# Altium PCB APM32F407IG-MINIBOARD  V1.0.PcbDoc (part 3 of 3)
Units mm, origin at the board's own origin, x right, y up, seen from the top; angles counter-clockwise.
Board outline 442.79 x 366.46 mm, 2 copper layers (Top Layer, Bottom Layer); 220 components, 190 nets, 1232 pads, 648 vias.
Unrouted connection lines stored in the file: 190.
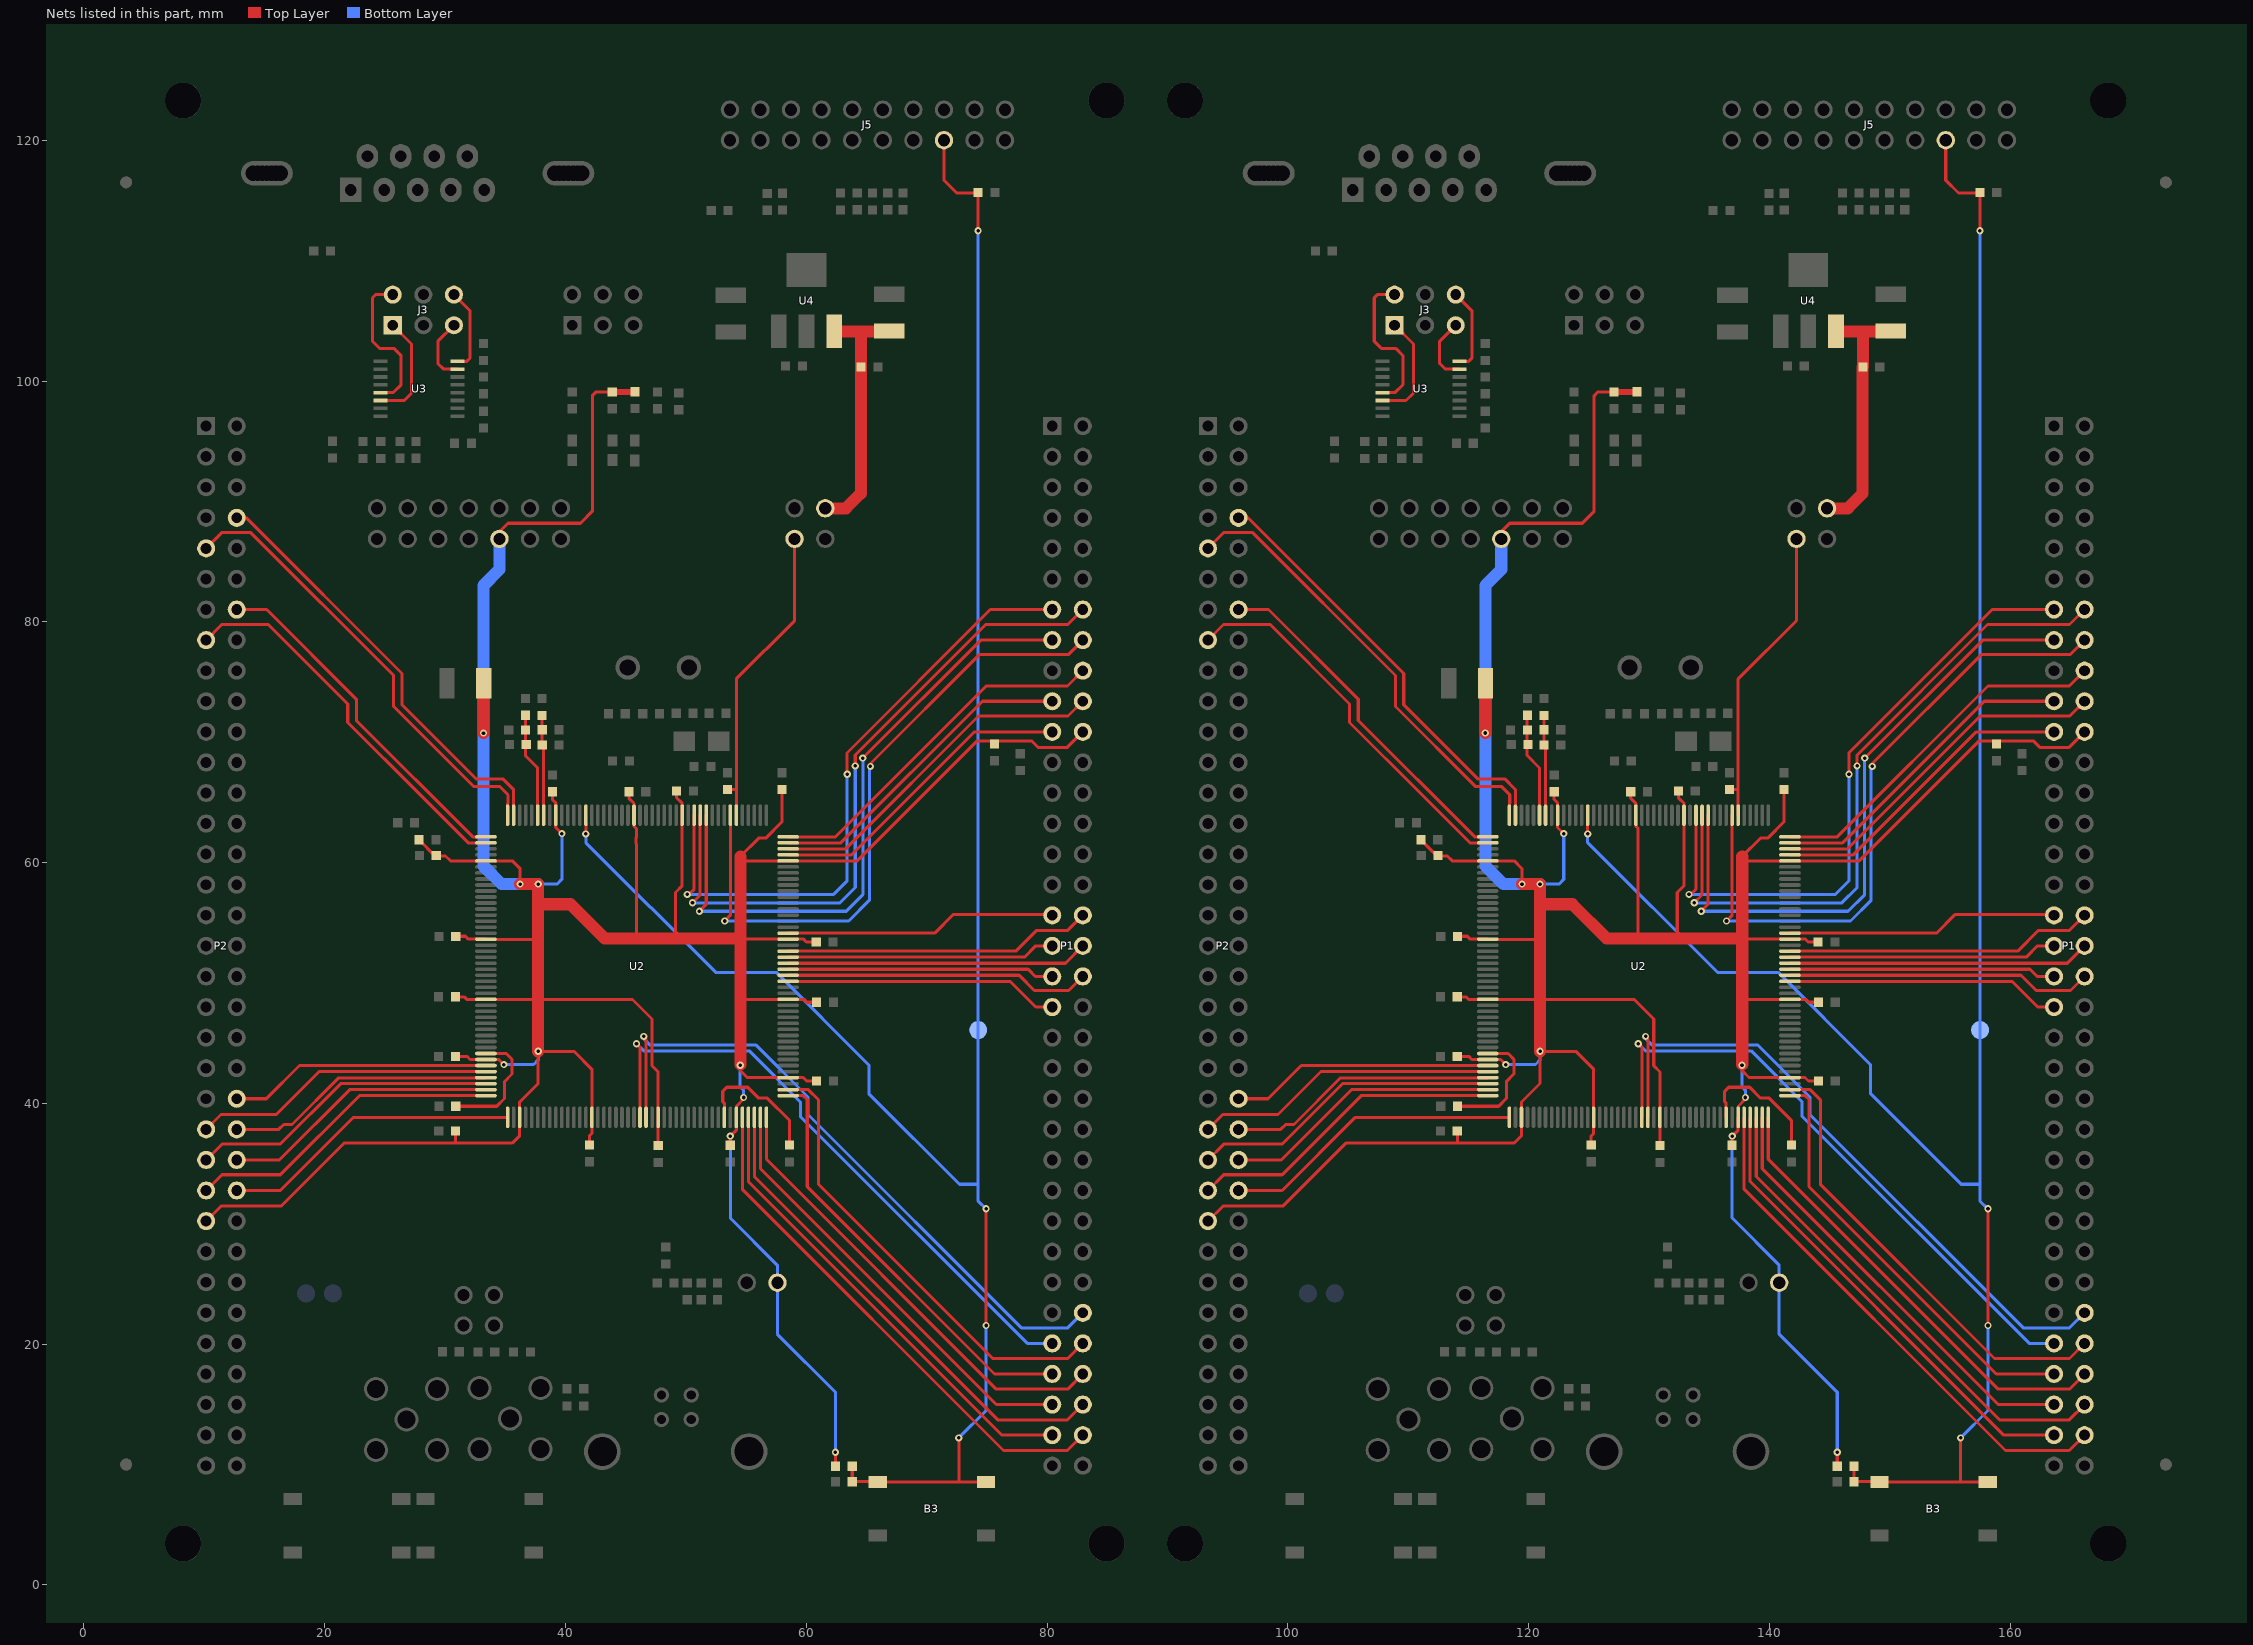
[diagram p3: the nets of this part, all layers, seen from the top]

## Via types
v1: diameter 0.6, hole 0.3, Top Layer to Bottom Layer, 648 vias

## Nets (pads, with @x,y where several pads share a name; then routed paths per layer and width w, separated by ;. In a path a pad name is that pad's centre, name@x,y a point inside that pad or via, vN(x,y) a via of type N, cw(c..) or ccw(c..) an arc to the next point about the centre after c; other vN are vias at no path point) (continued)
PG7: P1.61 U2.111 | length 103.6
  Top Layer w0.254: v1(45.896,44.96) 46.2,44.656 46.2,38.85 U2.111@46.19,38.84 ; v1(129.116,44.96) 129.42,44.656 129.42,38.85 U2.111@129.41,38.84
  Bottom Layer w0.254: v1(45.896,44.96) 46.496,44.36 55.27,44.36 59.51,40.12 59.51,38.91 78.359,20.061 P1.61@80.431,20.061 ; v1(129.116,44.96) 129.716,44.36 138.49,44.36 142.73,40.12 142.73,38.91 161.579,20.061 P1.61@163.651,20.061
PG8: P1.60 U2.112 | length 109
  Top Layer w0.254: U2.112@46.69,38.84 46.7,38.85 46.7,45.334 ; U2.112@129.91,38.84 129.92,38.85 129.92,45.334
  Bottom Layer w0.254: v1(46.5,45.56) 46.5,45.36 47,44.86 55.8,44.86 60.14,40.52 60.14,39.07 77.86,21.35 81.72,21.35 P1.60@82.971,22.601 ; v1(129.72,45.56) 129.72,45.36 130.22,44.86 139.02,44.86 143.36,40.52 143.36,39.07 161.08,21.35 164.94,21.35 P1.60@166.191,22.601
PG9: P1.39 U2.152 | length 45.7
  Top Layer w0.254: U2.152@58.49,50.14 76.93,50.14 79.069,48.001 P1.39@80.431,48.001 ; U2.152@141.71,50.14 160.15,50.14 162.289,48.001 P1.39@163.651,48.001
PG10: P1.38 U2.153 | length 51
  Top Layer w0.254: U2.153@58.49,50.64 77.68,50.64 78.95,49.37 81.8,49.37 P1.38@82.971,50.541 ; U2.153@141.71,50.64 160.9,50.64 162.17,49.37 165.02,49.37 P1.38@166.191,50.541
PG11: P1.37 U2.154 | length 44.4
  Top Layer w0.254: U2.154@58.49,51.14 78.43,51.14 79.03,50.541 P1.37@80.431,50.541 ; U2.154@141.71,51.14 161.65,51.14 162.25,50.541 P1.37@163.651,50.541
PG12: P1.36 U2.155 | length 50.2
  Top Layer w0.254: U2.155@58.49,51.64 81.53,51.64 P1.36@82.971,53.081 ; U2.155@141.71,51.64 164.75,51.64 P1.36@166.191,53.081
PG13: P1.35 U2.156 | length 44.7
  Top Layer w0.254: U2.156@58.49,52.14 78.12,52.14 79.061,53.081 P1.35@80.431,53.081 ; U2.156@141.71,52.14 161.34,52.14 162.281,53.081 P1.35@163.651,53.081
PG14: P1.34 U2.157 | length 51.4
  Top Layer w0.254: U2.157@58.49,52.64 77.41,52.64 79.14,54.37 81.72,54.37 P1.34@82.971,55.621 ; U2.157@141.71,52.64 160.63,52.64 162.36,54.37 164.94,54.37 P1.34@166.191,55.621
PG15: P1.33 U2.160 | length 45.2
  Top Layer w0.254: U2.160@58.49,54.14 60.306,54.14 60.307,54.141 70.661,54.141 72.19,55.67 80.381,55.67 P1.33@80.431,55.621 ; U2.160@141.71,54.14 143.526,54.14 143.527,54.141 153.881,54.141 155.41,55.67 163.601,55.67 P1.33@163.651,55.621
PH2: P2.8 U2.43 | length 72
  Top Layer w0.254: P2.8@12.69,88.641 13.479,88.641 26.41,75.71 26.41,73.11 32.558,66.961 34.788,66.961 35.69,66.06 U2.43@35.69,63.94 ; P2.8@95.91,88.641 96.699,88.641 109.63,75.71 109.63,73.11 115.778,66.962 118.008,66.962 118.91,66.06 U2.43@118.91,63.94
PH3: P2.9 U2.44 | length 75.7
  Top Layer w0.254: P2.9@10.15,86.101 11.486,87.437 13.823,87.437 25.72,75.54 25.72,72.96 32.35,66.33 34.51,66.33 35.217,65.623 35.217,64.94 35.19,64.913 U2.44@35.19,63.94 ; P2.9@93.37,86.101 94.706,87.437 97.043,87.437 108.94,75.54 108.94,72.96 115.57,66.33 117.73,66.33 118.437,65.623 118.437,64.94 118.41,64.913 U2.44@118.41,63.94
PH4: P2.14 U2.45 | length 59.1
  Top Layer w0.254: P2.14@12.69,81.021 15.179,81.021 22.63,73.57 22.63,71.81 32.3,62.14 U2.45@33.39,62.14 ; P2.14@95.91,81.021 98.399,81.021 105.85,73.57 105.85,71.81 115.52,62.14 U2.45@116.61,62.14
PH5: P2.15 U2.46 | length 64.4
  Top Layer w0.254: P2.15@10.15,78.481 11.439,79.77 15.32,79.77 21.91,73.18 21.91,71.64 27.88,65.67 31.91,61.64 U2.46@33.39,61.64 ; P2.15@93.37,78.481 94.659,79.77 98.54,79.77 105.13,73.18 105.13,71.64 111.1,65.67 115.13,61.64 U2.46@116.61,61.64
PH6: P2.46 U2.83 | length 43.7
  Top Layer w0.254: P2.46@12.701,40.37 P2.46@12.69,40.381 15.141,40.381 17.9,43.14 U2.83@33.39,43.14 ; P2.46@95.921,40.37 P2.46@95.91,40.381 98.361,40.381 101.12,43.14 U2.83@116.61,43.14
PH7: P2.47 U2.84 | length 50.5
  Top Layer w0.254: P2.47@10.15,37.841 11.379,39.07 15.97,39.07 19.54,42.64 U2.84@33.39,42.64 ; P2.47@93.37,37.841 94.599,39.07 99.19,39.07 102.76,42.64 U2.84@116.61,42.64
PH8: P2.48 U2.85 | length 45.2
  Top Layer w0.254: P2.48@12.761,37.77 P2.48@12.69,37.841 16.191,37.841 16.6,38.25 17.288,38.25 21.155,42.117 33.367,42.117 U2.85@33.39,42.14 ; P2.48@95.981,37.77 P2.48@95.91,37.841 99.411,37.841 99.82,38.25 100.508,38.25 104.375,42.117 116.587,42.117 U2.85@116.61,42.14
PH9: P2.49 U2.86 | length 51.7
  Top Layer w0.254: P2.49@10.15,35.301 11.459,36.61 16.29,36.61 21.32,41.64 U2.86@33.39,41.64 ; P2.49@93.37,35.301 94.679,36.61 99.51,36.61 104.54,41.64 U2.86@116.61,41.64
PH10: P2.50 U2.87 | length 46.2
  Top Layer w0.254: P2.50@12.69,35.301 16.231,35.301 22.07,41.14 U2.87@33.39,41.14 ; P2.50@95.91,35.301 99.451,35.301 105.29,41.14 U2.87@116.61,41.14
PH11: P2.51 U2.88 | length 53
  Top Layer w0.254: P2.51@10.15,32.761 11.459,34.07 16.31,34.07 22.88,40.64 U2.88@33.39,40.64 ; P2.51@93.37,32.761 94.679,34.07 99.53,34.07 106.1,40.64 U2.88@116.61,40.64
PH12: P2.52 U2.89 | length 50
  Top Layer w0.254: P2.52@12.69,32.761 16.311,32.761 22.39,38.84 U2.89@35.19,38.84 ; P2.52@95.91,32.761 99.531,32.761 105.61,38.84 U2.89@118.41,38.84
PH13: P1.68 U2.128 | length 87.6
  Top Layer w0.254: U2.128@54.69,38.84 54.69,32.86 76.39,11.16 81.69,11.16 P1.68@82.971,12.441 ; U2.128@137.91,38.84 137.91,32.86 159.61,11.16 164.91,11.16 P1.68@166.191,12.441
PH14: P1.67 U2.129 | length 78.6
  Top Layer w0.254: U2.129@55.19,38.84 55.19,33.51 76.259,12.441 P1.67@80.431,12.441 ; U2.129@138.41,38.84 138.41,33.51 159.479,12.441 P1.67@163.651,12.441
PH15: P1.66 U2.130 | length 82.2
  Top Layer w0.254: U2.130@55.69,38.84 55.69,33.92 75.9,13.71 81.7,13.71 P1.66@82.971,14.981 ; U2.130@138.91,38.84 138.91,33.92 159.12,13.71 164.92,13.71 P1.66@166.191,14.981
PI0: P1.65 U2.131 | length 73.2
  Top Layer w0.254: U2.131@56.19,38.84 56.19,34.58 75.789,14.981 P1.65@80.431,14.981 ; U2.131@139.41,38.84 139.41,34.58 159.009,14.981 P1.65@163.651,14.981
PI1: P1.64 U2.132 | length 76.4
  Top Layer w0.254: U2.132@56.69,38.84 56.69,35.36 75.79,16.26 81.71,16.26 P1.64@82.971,17.521 ; U2.132@139.91,38.84 139.91,35.36 159.01,16.26 164.93,16.26 P1.64@166.191,17.521
PI2: P1.63 U2.133 | length 71.5
  Top Layer w0.254: U2.133@58.49,40.64 59.76,40.64 60.08,40.32 60.08,33.08 75.639,17.521 P1.63@80.431,17.521 ; U2.133@141.71,40.64 142.98,40.64 143.3,40.32 143.3,33.08 158.859,17.521 P1.63@163.651,17.521
PI3: P1.62 U2.134 | length 76.7
  Top Layer w0.254: U2.134@58.49,41.14 60.17,41.14 61.02,40.29 61.02,33.28 75.49,18.81 81.72,18.81 P1.62@82.971,20.061 ; U2.134@141.71,41.14 143.39,41.14 144.24,40.29 144.24,33.28 158.71,18.81 164.94,18.81 P1.62@166.191,20.061
PI4: P1.21 U2.173 | length 52.3
  Top Layer w0.254: U2.173@58.49,60.64 63.75,60.64 73.971,70.861 P1.21@80.431,70.861 ; U2.173@141.71,60.64 146.97,60.64 157.191,70.861 P1.21@163.651,70.861
PI5: P1.20 U2.174 | length 59.1
  Top Layer w0.254: U2.174@58.49,61.14 63.27,61.14 74.3,72.17 81.74,72.17 P1.20@82.971,73.401 ; U2.174@141.71,61.14 146.49,61.14 157.52,72.17 164.96,72.17 P1.20@166.191,73.401
PI6: P1.19 U2.175 | length 53.6
  Top Layer w0.254: U2.175@58.49,61.64 62.87,61.64 74.631,73.401 P1.19@80.431,73.401 ; U2.175@141.71,61.64 146.09,61.64 157.851,73.401 P1.19@163.651,73.401
PI7: P1.18 U2.176 | length 60.4
  Top Layer w0.254: U2.176@58.49,62.14 62.42,62.14 74.95,74.67 81.7,74.67 P1.18@82.971,75.941 ; U2.176@141.71,62.14 145.64,62.14 158.17,74.67 164.92,74.67 P1.18@166.191,75.941
PI8: P1.16 U2.7 | length 110.1
  Top Layer w0.254: v1(53.22,55.15) 53.69,55.62 U2.7@53.69,63.94 ; v1(65.33,67.99) 65.33,68.227 74.373,77.27 81.76,77.27 P1.16@82.971,78.481 ; v1(136.44,55.15) 136.91,55.62 U2.7@136.91,63.94 ; v1(148.55,67.99) 148.55,68.227 157.593,77.27 164.98,77.27 P1.16@166.191,78.481
  Bottom Layer w0.254: v1(53.22,55.15) 63.52,55.15 65.24,56.87 65.24,67.98 65.25,67.99 v1(65.33,67.99) ; v1(136.44,55.15) 146.74,55.15 148.46,56.87 148.46,67.98 148.47,67.99 v1(148.55,67.99)
PI9: P1.15 U2.11 | length 112.5
  Top Layer w0.254: v1(51.12,55.96) 51.69,56.53 U2.11@51.69,63.94 ; v1(64.7,68.68) 74.501,78.481 P1.15@80.431,78.481 77.691,78.481 ; v1(134.34,55.96) 134.91,56.53 U2.11@134.91,63.94 ; v1(147.92,68.68) 157.721,78.481 P1.15@163.651,78.481 160.911,78.481
  Bottom Layer w0.254: v1(51.12,55.96) 63.32,55.96 64.697,57.337 64.697,68.677 v1(64.7,68.68) ; v1(134.34,55.96) 146.54,55.96 147.917,57.337 147.917,68.677 v1(147.92,68.68)
PI10: P1.14 U2.12 | length 113
  Top Layer w0.254: v1(50.55,56.66) 51.19,57.3 U2.12@51.19,63.94 ; v1(64.07,68.03) 64.07,68.937 74.903,79.77 81.72,79.77 P1.14@82.971,81.021 ; v1(133.77,56.66) 134.41,57.3 U2.12@134.41,63.94 ; v1(147.29,68.03) 147.29,68.937 158.123,79.77 164.94,79.77 P1.14@166.191,81.021
  Bottom Layer w0.254: v1(50.55,56.66) 62.8,56.66 64.07,57.93 v1(64.07,68.03) ; v1(133.77,56.66) 146.02,56.66 147.29,57.93 v1(147.29,68.03)
PI11: P1.13 U2.13 | length 106.6
  Top Layer w0.254: v1(50.11,57.36) 50.26,57.36 50.69,57.79 U2.13@50.69,63.94 ; v1@63.38,67.317 63.38,69.11 75.291,81.021 P1.13@80.431,81.021 ; v1(133.33,57.36) 133.48,57.36 133.91,57.79 U2.13@133.91,63.94 ; v1@146.6,67.317 146.6,69.11 158.511,81.021 P1.13@163.651,81.021
  Bottom Layer w0.254: v1(50.11,57.36) 62.27,57.36 63.4,58.49 v1(63.4,67.34) ; v1(133.33,57.36) 145.49,57.36 146.62,58.49 v1(146.62,67.34)
T-RESET#: B3.2 B3.3 C3.2 J5.15 R5.2 R26.1 TP7.1 U2.31 | length 349.4
  Top Layer w0.254: v1(41.69,62.38) U2.31@41.69,63.24 ; R5.2@63.82,9.85 C3.2@63.82,8.57 65.917,8.57 B3.2@65.93,8.557 72.66,8.557 ; J5.15@71.434,120.005 71.434,116.669 72.49,115.613 74.23,115.613 R26.1@74.272,115.655 v1(74.272,112.482) ; v1(72.67,12.21) 72.67,8.567 72.66,8.557 ; B3.3@74.93,8.557 72.66,8.557 ; v1(74.94,21.55) v1(74.94,31.25) ; v1(124.91,62.38) U2.31@124.91,63.24 ; R5.2@147.04,9.85 C3.2@147.04,8.57 149.137,8.57 B3.2@149.15,8.557 155.88,8.557 ; J5.15@154.654,120.005 154.654,116.669 155.71,115.613 157.45,115.613 R26.1@157.492,115.655 v1(157.492,112.482) ; v1(155.89,12.21) 155.89,8.567 155.88,8.557 ; B3.3@158.15,8.557 155.88,8.557 ; v1(158.16,21.55) v1(158.16,31.25)
  Bottom Layer w0.254: v1(41.69,62.38) 41.69,61.66 52.47,50.88 57.51,50.88 65.2,43.19 65.2,40.8 72.72,33.28 74.282,33.28 ; v1(72.67,12.21) 74.94,14.48 v1(74.94,21.55) ; 74.262,36.24 74.282,36.22 ; v1(74.272,112.482) 74.282,112.472 TP7.1@74.282,46.09 74.282,36.22 ; v1@74.925,31.235 74.282,31.878 74.282,33.28 ; v1(124.91,62.38) 124.91,61.66 135.69,50.88 140.73,50.88 148.42,43.19 148.42,40.8 155.94,33.28 157.502,33.28 ; v1(155.89,12.21) 158.16,14.48 v1(158.16,21.55) ; 157.482,36.24 157.502,36.22 ; v1(157.492,112.482) 157.502,112.472 TP7.1@157.502,46.09 157.502,36.22 ; v1@158.145,31.235 157.502,31.878 157.502,33.28 ; 74.282,33.28 74.282,36.22 ; 157.502,33.28 157.502,36.22
T-VBAT: C28.2 J9.2 U2.6 | length 51.4
  Top Layer w0.254: C28.2@53.46,66.07 54.18,66.07 54.19,66.06 ; U2.6@54.19,63.94 54.19,66.06 ; J9.2@59.03,86.89 59.03,80.1 54.19,75.26 54.19,66.06 ; C28.2@136.68,66.07 137.4,66.07 137.41,66.06 ; U2.6@137.41,63.94 137.41,66.06 ; J9.2@142.25,86.89 142.25,80.1 137.41,75.26 137.41,66.06
U1_RX: J3.2 U3.13 | length 25.4
  Top Layer w0.254: U3.13@24.635,99.034 25.673,99.034 26.344,99.705 26.344,102.105 25.734,102.715 24.544,102.715 23.96,103.299 23.96,106.915 24.222,107.177 J3.2@25.651,107.177 J3.2@25.623,107.205 ; U3.13@107.855,99.034 108.893,99.034 109.564,99.705 109.564,102.105 108.954,102.715 107.764,102.715 107.18,103.299 107.18,106.915 107.442,107.177 J3.2@108.871,107.177 J3.2@108.843,107.205
U1_TX: J3.1 U3.14 | length 18.5
  Top Layer w0.254: U3.14@24.635,98.384 26.603,98.384 27.214,98.995 27.214,103.073 J3.1@25.651,104.637 ; U3.14@107.855,98.384 109.823,98.384 110.434,98.995 110.434,103.073 J3.1@108.871,104.637
  Bottom Layer w0.254: J3.1@25.563,104.725 J3.1@25.651,104.637 ; J3.1@108.783,104.725 J3.1@108.871,104.637
U2_RX: J3.6 U3.8 | length 13.9
  Top Layer w0.254: J3.6@30.731,107.177 32.064,105.843 32.064,101.897 31.801,101.634 U3.8@31.035,101.634 ; J3.6@113.951,107.177 115.284,105.843 115.284,101.897 115.021,101.634 U3.8@114.255,101.634
U2_TX: J3.5 U3.7 | length 11.1
  Top Layer w0.254: J3.5@30.731,104.637 29.397,103.303 29.397,101.462 29.875,100.984 U3.7@31.035,100.984 ; J3.5@113.951,104.637 112.617,103.303 112.617,101.462 113.095,100.984 U3.7@114.255,100.984
VCAP_1: C18.2 U2.81 | length 20.4
  Top Layer w0.254: C18.2@30.89,39.75 C18.2@30.88,39.76 34.29,39.76 34.93,40.4 34.93,41.803 35.56,42.433 35.56,43.66 35.08,44.14 U2.81@33.39,44.14 ; C18.2@114.11,39.75 C18.2@114.1,39.76 117.51,39.76 118.15,40.4 118.15,41.803 118.78,42.433 118.78,43.66 118.3,44.14 U2.81@116.61,44.14
VCAP_2: C19.1 U2.125 | length 22.2
  Top Layer w0.254: U2.125@53.19,38.84 53.19,40.013 53.063,40.14 53.063,41.003 53.4,41.34 55.14,41.34 56.05,40.43 56.77,40.43 58.61,38.59 C19.1@58.61,36.527 ; U2.125@136.41,38.84 136.41,40.013 136.283,40.14 136.283,41.003 136.62,41.34 138.36,41.34 139.27,40.43 139.99,40.43 141.83,38.59 C19.1@141.83,36.527
VCC5.0: C1.2 C2.1 J15.1 U4.3 | length 43.1
  Top Layer w1: J15.1@61.58,89.43 63.293,89.43 64.53,90.667 C1.2@64.53,101.173 ; U4.3@62.32,104.13 64.47,104.13 ; C1.2@64.55,101.173 64.55,104.05 64.47,104.13 ; C2.1@66.88,104.166 66.844,104.13 64.47,104.13 ; J15.1@144.8,89.43 146.513,89.43 147.75,90.667 C1.2@147.75,101.173 ; U4.3@145.54,104.13 147.69,104.13 ; C1.2@147.77,101.173 147.77,104.05 147.69,104.13 ; C2.1@150.1,104.166 150.064,104.13 147.69,104.13
VDD: C21.1 CF1.1 CF2.1 CF3.1 CF4.1 CF5.1 CF6.1 CF7.1 CF8.1 CF9.1 CF10.1 CF11.1 CF12.1 CF13.1 CF14.1 CF15.1 J6.2 J10.1 P1.22 P2.53 R5.1 R10.2 R11.1 R12.1 R32.2 U2.15 U2.23 U2.36 U2.49 U2.62 U2.72 U2.82 U2.91 U2.103 U2.114 U2.127 U2.136 U2.149 U2.159 U2.172 | length 687.1
  Top Layer w0.254: P2.53@10.15,30.221 11.389,31.46 16.37,31.46 21.6,36.69 30.8,36.69 ; R32.2@27.833,61.89 29.143,60.58 CF11.1@29.267,60.58 ; CF11.1@29.39,60.55 30.03,60.55 30.44,60.14 U2.49@33.39,60.14 35.58,60.14 36.23,59.49 v1(36.23,58.21) ; CF2.1@30.85,48.85 31.582,48.85 31.792,48.64 U2.72@33.39,48.64 ; CF15.1@30.85,43.9 31.81,43.9 32.07,43.64 U2.82@33.39,43.64 34.46,43.64 v1(34.88,43.22) ; CF10.1@30.861,37.71 30.861,36.751 30.8,36.69 ; CF1.1@30.88,53.87 30.89,53.88 31.692,53.88 31.932,53.64 U2.62@33.39,53.64 ; U2.62@34.06,53.62 37.73,53.62 ; U2.72@34.07,48.62 37.71,48.62 37.73,48.64 ; J6.2@34.51,86.89 34.51,87.48 35.22,88.19 41.24,88.19 42.23,89.18 42.23,98.78 42.55,99.1 R12.1@43.877,99.1 ; 37.73,48.62 45.56,48.62 47.18,47 47.18,43.13 47.7,42.61 47.7,38.85 U2.114@47.69,38.84 47.69,36.51 CF4.1@47.71,36.49 ; CF14.1@38.91,65.88 38.91,65.24 39.19,64.96 U2.36@39.19,63.94 39.19,62.92 v1(39.7,62.41) ; CF3.1@41.98,36.54 41.98,37.292 42.19,37.501 U2.103@42.19,38.84 42.19,42.84 40.71,44.32 37.73,44.32 37.73,41.651 36.19,40.112 U2.91@36.19,38.84 36.19,37.31 35.57,36.69 30.8,36.69 ; CF12.1@45.262,65.88 45.262,65.348 45.69,64.92 U2.23@45.69,63.94 45.69,63.015 45.88,62.825 45.88,62.107 45.863,62.09 45.863,61.57 45.88,61.553 45.88,53.77 45.81,53.7 ; 49.13,53.7 49.13,57.51 49.69,58.07 U2.15@49.69,63.94 49.69,64.93 49.222,65.398 CF9.1@49.222,65.94 ; CF5.1@53.68,36.518 v1@53.68,37.26 ; v1@53.695,37.275 54.19,37.77 U2.127@54.19,38.84 54.213,38.863 54.213,39.788 54.79,40.365 v1(54.79,40.49) ; v1@54.53,43.22 54.53,42.702 55.092,42.14 U2.136@58.49,42.14 59.74,42.14 60.03,41.85 CF13.1@60.862,41.85 ; 54.53,48.633 54.537,48.64 U2.149@58.49,48.64 59.82,48.64 60.06,48.4 CF6.1@60.853,48.4 ; 54.53,53.71 54.6,53.64 U2.159@58.49,53.64 59.78,53.64 60.01,53.41 CF7.1@60.833,53.41 ; 54.53,54.57 54.58,54.62 ; CF8.1@57.99,66.071 57.99,63.38 56.64,62.03 56.04,62.03 54.53,60.52 54.91,60.14 U2.172@58.49,60.14 64.24,60.14 74.21,70.11 78.71,70.11 79.25,69.57 81.68,69.57 P1.22@82.971,70.861 ; v1(62.42,11.02) 62.423,11.017 R5.1@62.423,9.85 ; P2.53@93.37,30.221 94.609,31.46 99.59,31.46 104.82,36.69 114.02,36.69 ; R32.2@111.053,61.89 112.363,60.58 CF11.1@112.487,60.58 ; CF11.1@112.61,60.55 113.25,60.55 113.66,60.14 U2.49@116.61,60.14 118.8,60.14 119.45,59.49 v1(119.45,58.21) ; CF15.1@114.07,43.9 115.03,43.9 115.29,43.64 U2.82@116.61,43.64 117.68,43.64 v1(118.1,43.22) ; CF2.1@114.07,48.85 114.801,48.85 115.011,48.64 U2.72@116.61,48.64 ; CF10.1@114.081,37.71 114.081,36.751 114.02,36.69 ; CF1.1@114.1,53.87 114.11,53.88 114.911,53.88 115.151,53.64 U2.62@116.61,53.64 ; U2.62@117.28,53.62 120.95,53.62 ; U2.72@117.29,48.62 120.93,48.62 120.95,48.64 ; J6.2@117.73,86.89 117.73,87.48 118.44,88.19 124.46,88.19 125.45,89.18 125.45,98.78 125.77,99.1 R12.1@127.097,99.1 ; 120.95,48.62 128.78,48.62 130.4,47 130.4,43.13 130.92,42.61 130.92,38.85 U2.114@130.91,38.84 130.91,36.51 CF4.1@130.93,36.49 ; CF14.1@122.13,65.88 122.13,65.24 122.41,64.96 U2.36@122.41,63.94 122.41,62.92 v1(122.92,62.41) ; CF3.1@125.2,36.54 125.2,37.292 125.41,37.502 U2.103@125.41,38.84 125.41,42.84 123.93,44.32 120.95,44.32 120.95,41.652 119.41,40.112 U2.91@119.41,38.84 119.41,37.31 118.79,36.69 114.02,36.69 ; CF12.1@128.481,65.88 128.481,65.349 128.91,64.92 U2.23@128.91,63.94 128.91,63.015 129.1,62.825 129.1,62.107 129.083,62.09 129.083,61.57 129.1,61.553 129.1,53.77 129.03,53.7 ; 132.35,53.7 132.35,57.51 132.91,58.07 U2.15@132.91,63.94 132.91,64.93 132.441,65.399 CF9.1@132.441,65.94 ; CF5.1@136.9,36.519 v1@136.9,37.26 ; v1@136.915,37.275 137.41,37.77 U2.127@137.41,38.84 137.433,38.863 137.433,39.788 138.01,40.365 v1(138.01,40.49) ; v1@137.75,43.22 137.75,42.702 138.312,42.14 U2.136@141.71,42.14 142.96,42.14 143.25,41.85 CF13.1@144.081,41.85 ; 137.75,48.633 137.757,48.64 U2.149@141.71,48.64 143.04,48.64 143.28,48.4 CF6.1@144.073,48.4 ; 137.75,53.71 137.82,53.64 U2.159@141.71,53.64 143,53.64 143.23,53.41 CF7.1@144.053,53.41 ; 137.75,54.57 137.8,54.62 ; CF8.1@141.21,66.072 141.21,63.38 139.86,62.03 139.26,62.03 137.75,60.52 138.13,60.14 U2.172@141.71,60.14 147.46,60.14 157.43,70.11 161.93,70.11 162.47,69.57 164.9,69.57 P1.22@166.191,70.861 ; v1(145.64,11.02) 145.643,11.017 R5.1@145.643,9.85
  Top Layer w0.5: R12.1@43.877,99.1 45.77,99.1 R11.1@45.78,99.11 ; R12.1@127.097,99.1 128.99,99.1 R11.1@129,99.11
  Top Layer w1: v1(33.186,70.76) 33.186,73.53 ; v1(36.23,58.21) v1(37.73,58.21) 37.73,56.54 ; v1@37.73,44.32 37.73,48.62 37.73,48.64 37.73,53.62 37.73,56.54 ; v1@54.53,43.22 54.53,48.633 54.53,49.62 54.53,53.4 ; 54.53,60.52 54.53,54.57 54.53,53.71 52.594,53.71 52.584,53.7 49.13,53.7 45.81,53.7 43.26,53.7 40.42,56.54 37.73,56.54 ; v1(116.406,70.76) 116.406,73.53 ; v1(119.45,58.21) v1(120.95,58.21) 120.95,56.54 ; v1@120.95,44.32 120.95,48.62 120.95,48.64 120.95,53.62 120.95,56.54 ; v1@137.75,43.22 137.75,48.633 137.75,49.62 137.75,53.4 ; 137.75,60.52 137.75,54.57 137.75,53.71 135.814,53.71 135.804,53.7 132.35,53.7 129.03,53.7 126.48,53.7 123.64,56.54 120.95,56.54
  Bottom Layer w0.254: v1(34.88,43.22) 37.35,43.22 37.74,43.61 v1(37.74,44.33) ; v1(37.73,58.21) 39.3,58.21 39.7,58.61 v1(39.7,62.41) ; v1(53.69,37.28) 53.69,30.47 57.6,26.56 J10.1@57.6,25.105 57.6,20.83 62.42,16.01 v1(62.42,11.02) ; v1(54.51,43.16) 54.51,41.37 54.79,41.09 v1(54.79,40.49) ; v1(118.1,43.22) 120.57,43.22 120.96,43.61 v1(120.96,44.33) ; v1(120.95,58.21) 122.52,58.21 122.92,58.61 v1(122.92,62.41) ; v1(136.91,37.28) 136.91,30.47 140.82,26.56 J10.1@140.82,25.105 140.82,20.83 145.64,16.01 v1(145.64,11.02) ; v1(137.73,43.16) 137.73,41.37 138.01,41.09 v1(138.01,40.49)
  Bottom Layer w1: J6.2@34.51,86.89 34.51,84.34 33.19,83.02 33.19,59.72 34.7,58.21 v1(36.23,58.21) v1(37.73,58.21) ; J6.2@117.73,86.89 117.73,84.34 116.41,83.02 116.41,59.72 117.92,58.21 v1(119.45,58.21) v1(120.95,58.21)
VDDA: C17.2 C27.2 L1.1 U2.39 | length 17.7
  Top Layer w0.254: L1.1@36.66,72.25 C27.2@36.66,69.73 ; C27.2@36.74,69.81 C27.2@36.66,69.73 ; U2.39@37.69,63.94 37.69,67.86 36.66,68.89 C27.2@36.66,69.73 ; L1.1@119.88,72.25 C27.2@119.88,69.73 ; C27.2@119.96,69.81 C27.2@119.88,69.73 ; U2.39@120.91,63.94 120.91,67.86 119.88,68.89 C27.2@119.88,69.73
VREF+: C25.2 C26.2 L2.1 U2.38 | length 16.7
  Top Layer w0.254: L2.1@38.06,72.23 C25.2@38.062,69.78 38.19,69.65 U2.38@38.19,63.94 ; L2.1@121.28,72.23 C25.2@121.281,69.78 121.41,69.65 U2.38@121.41,63.94
pads on no net: J1.6 J1.7 J1.8 J1.9 J5.17 J5.19 P2.17
copper on no net: | length 62.8
  Top Layer w0.3: 4.75,10 ccw(c3.5,10) 4.75,10 ; 4.75,116.505 ccw(c3.5,116.505) 4.75,116.505 ; 174.19,10 ccw(c172.94,10) 174.19,10 ; 174.19,116.505 ccw(c172.94,116.505) 174.19,116.505
  Bottom Layer w0.3: 4.74,9.99 ccw(c3.49,9.99) 4.74,9.99 ; 4.74,116.515 ccw(c3.49,116.515) 4.74,116.515 ; 174.2,9.99 ccw(c172.95,9.99) 174.2,9.99 ; 174.2,116.515 ccw(c172.95,116.515) 174.2,116.515

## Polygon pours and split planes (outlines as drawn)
GND on Top Layer "Bottom Layer-No Net 1" (solid, remove dead copper, pour order 16): 5,126.505 5,0 88.22,0 88.22,1.5 88.22,126.505 5,126.505
NetC24_2 on Top Layer "Bottom Layer-No Net 1" (solid, pour order 12): 42.52,0.58 57.01,0.58 57.01,13.24 56.92,13.15 53.36,13.15 53.01,13.15 52.22,12.36 52.16,12.3 47.64,12.3 46.09,12.3 45.16,13.23 44.52,13.87 44.52,16.23 44.52,17.41 41.15,17.41 41.15,0.74 41.24,0.65 41.31,0.58 42.5,0.58
NetC24_2 on Top Layer "Bottom Layer-No Net" (solid, remove dead copper, pour order 10): 58.49,0.665 58.49,18.515 58.49,18.635 58.11,19.015 57.98,19.145 41.11,19.145 41.11,0.695 41.16,0.645 41.18,0.665 58.49,0.665
NetC24_2 on Top Layer "Bottom Layer-No Net" (solid, remove dead copper, pour order 9): 141.71,0.665 141.71,18.515 141.71,18.635 141.33,19.015 141.2,19.145 124.33,19.145 124.33,0.695 124.38,0.645 124.4,0.665 141.71,0.665
NetC24_2 on Top Layer "Bottom Layer-No Net 1" (solid, pour order 11): 125.74,0.58 140.23,0.58 140.23,13.24 140.14,13.15 136.58,13.15 136.23,13.15 135.44,12.36 135.38,12.3 130.86,12.3 129.31,12.3 128.38,13.23 127.74,13.87 127.74,16.23 127.74,17.41 124.37,17.41 124.37,0.74 124.46,0.65 124.53,0.58 125.72,0.58
GND on Top Layer "Bottom Layer-No Net 1" (solid, remove dead copper, pour order 15): 88.22,126.505 88.22,0 171.44,0 171.44,1.5 171.44,126.505 88.22,126.505
GND on Bottom Layer "Bottom Layer-No Net 1" (solid, remove dead copper, pour order 14): 5,126.505 5,0 88.22,0 88.23,0.01 88.22,0.02 88.22,126.505 5,126.505
GND on Bottom Layer "Bottom Layer-No Net 1" (solid, remove dead copper, pour order 13): 88.22,126.505 88.22,0 171.44,0 171.45,0.01 171.44,0.02 171.44,126.505 88.22,126.505

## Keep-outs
Keep-Out Layer:
  circle w0.127: c173.94,5 r1
  circle w0.127: c173.94,121.505 r1
  circle w0.127: c2.5,5 r1
  circle w0.127: c2.5,121.505 r1
  lines w0.254: 88.21,100.091 87.1,100.091 87.1,101.151 88.22,101.151 ; 88.22,0 88.22,1.5 ; 171.43,100.091 170.32,100.091 170.32,101.151 171.44,101.151 ; 171.44,99.92 171.44,101.151 ; 171.44,100.09 171.44,1.5 ; 5,1.5 ccw(c6.5,1.5) 6.5,0 86.72,0 ccw(c86.72,1.5) 88.22,1.5 ; 5,1.5 5,0 0,0 0,126.505 5,126.505 ; 5,1.5 5,100.09 ; 5,100.09 5,101.15 ; 5,100.09 6.12,100.09 6.12,101.15 5,101.15 ; 5,101.15 5,125.005 ; 5,125.005 cw(c6.5,125.005) 6.5,126.505 ; 5,125.005 5,126.505 ; 5,126.505 6.5,126.505 ; 6.5,126.505 86.72,126.505 ; 86.72,126.505 cw(c86.72,125.005) 88.22,125.005 ; 86.72,126.505 88.22,126.505 ; 88.22,1.5 ccw(c89.72,1.5) 89.72,0 169.94,0 ccw(c169.94,1.5) 171.44,1.5 ; 88.22,1.5 88.22,100.09 ; 88.22,1.5 88.22,100.09 ; 88.22,100.09 89.34,100.09 89.34,101.15 88.22,101.15 ; 88.22,100.09 88.22,101.15 ; 88.22,101.151 88.22,125.005 ; 88.22,101.15 88.22,125.005 ; 88.22,125.005 cw(c89.72,125.005) 89.72,126.505 ; 88.22,125.005 88.22,126.505 ; 88.22,126.505 89.72,126.505 ; 89.72,126.505 169.94,126.505 cw(c169.94,125.005) 171.44,125.005 ; 171.44,1.5 171.44,0 176.44,0 176.44,126.505 171.44,126.505 171.44,125.005 ; 171.44,101.151 171.44,125.005

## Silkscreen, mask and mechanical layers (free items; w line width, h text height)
Top Overlay:
  drawing of 9488 lines, arcs and shapes, not listed
  text "JTAG" at 70.8,112.83 h2
  text "JTAG" at 154.02,112.83 h2
  text "BOOT" at 40.45,111.48 h2
  text "BOOT" at 123.67,111.48 h2
  text "USART" at 24.65,109.76 h2
  text "1" at 40.21,109.755 h1.02
  text "USART" at 107.87,109.76 h2
  text "1" at 123.43,109.755 h1.02
  text "0" at 45.33,109.695 h1.02
  text "0" at 128.55,109.695 h1.02
  text "BOOT1" at 42.33,108.7 h0.7
  text "BOOT1" at 125.55,108.7 h0.7
  text "0" at 47.52,105.64 h1.02
  text "0" at 130.74,105.64 h1.02
  text "1" at 38.23,105.59 h1.02
  text "1" at 121.45,105.59 h1.02
  text "USART2" at 35.34,104.61 h0.8 r90
  text "USART2" at 118.56,104.61 h0.8 r90
  text "USART1" at 21.24,104.18 h0.8 r90
  text "USART1" at 104.46,104.18 h0.8 r90
  text "BOOT0" at 42.14,102.52 h0.7
  text "BOOT0" at 125.36,102.52 h0.7
  text "PE5" at 84.48,95.85 h1.5
  text "PE5" at 167.7,95.85 h1.5
  text "PC1" at 14.32,95.79 h1.5
  text "PC1" at 97.54,95.79 h1.5
  text "PC0" at 6.123,95.75 h1.5
  text "PC0" at 89.343,95.75 h1.5
  text "PE6" at 76.518,95.74 h1.5
  text "PE6" at 159.738,95.74 h1.5
  text "PE3" at 84.48,93.31 h1.5
  text "PE3" at 167.7,93.31 h1.5
  text "PC3" at 14.32,93.26 h1.5
  text "PC3" at 97.54,93.26 h1.5
  text "PC2" at 6.131,93.217 h1.5
  text "PC2" at 89.351,93.217 h1.5
  text "PE4" at 76.521,93.2 h1.5
  text "PE4" at 159.741,93.2 h1.5
  text "PF6" at 84.48,90.77 h1.5
  text "PF6" at 167.7,90.77 h1.5
  text "PA1" at 14.32,90.731 h1.5
  text "PA1" at 97.54,90.731 h1.5
  text "PA0" at 6.198,90.684 h1.5
  text "PA0" at 89.418,90.684 h1.5
  text "PE2" at 76.528,90.661 h1.5
  text "PE2" at 159.748,90.661 h1.5
  text "PA2" at 6.206,88.29 h1.5
  text "PA2" at 89.426,88.29 h1.5
  text "PH2" at 14.32,88.26 h1.5
  text "PH2" at 97.54,88.26 h1.5
  text "PF4" at 84.48,88.23 h1.5
  text "PF4" at 167.7,88.23 h1.5
  text "PF5" at 76.585,88.121 h1.5
  text "PF5" at 159.805,88.121 h1.5
  text "PF2" at 84.48,85.69 h1.5
  text "PF2" at 167.7,85.69 h1.5
  text "PF3" at 76.593,85.581 h1.5
  text "PF3" at 159.813,85.581 h1.5
  text "PH3" at 6.121,85.51 h1.5
  text "PF10" at 14.32,85.53 h1.5
  text "PH3" at 89.341,85.51 h1.5
  text "PF10" at 97.54,85.53 h1.5
  text "PF8" at 14.32,83.163 h1.5
  text "PF0" at 84.48,83.15 h1.5
  text "PF8" at 97.54,83.163 h1.5
  text "PF0" at 167.7,83.15 h1.5
  text "PF9" at 6.268,83.108 h1.5
  text "PF9" at 89.488,83.108 h1.5
  text "PF1" at 76.778,83.042 h1.5
  text "PF1" at 159.998,83.042 h1.5
  text "VDD" at 34.97,82.32 h1 r90
  text "VDD" at 118.19,82.32 h1 r90
  text "U1TX" at 29.93,81.64 h1 r90
  text "U1TX" at 113.15,81.64 h1 r90
  text "U2RX" at 24.93,81.61 h1 r90
  text "U2RX" at 108.15,81.61 h1 r90
  text "U2TX" at 27.36,81.57 h1 r90
  text "U2TX" at 110.58,81.57 h1 r90
  text "U1RX" at 32.484,81.5 h1 r90
  text "U1RX" at 115.704,81.5 h1 r90
  text "VDDA" at 37.53,81.48 h1 r90
  text "VDDA" at 120.75,81.48 h1 r90
  text "VBAT" at 59.46,81.42 h1 r90
  text "VBAT" at 142.68,81.42 h1 r90
  text "VCC5.0" at 62.21,80.68 h1 r90
  text "VCC5.0" at 145.43,80.68 h1 r90
  text "PF7" at 6.271,80.61 h1.5
  text "PF7" at 89.491,80.61 h1.5
  text "PH4" at 14.32,80.57 h1.5
  text "PI11" at 76.479,80.56 h1.5
  text "PH4" at 97.54,80.57 h1.5
  text "PI11" at 159.699,80.56 h1.5
  text "PI10" at 84.48,80.53 h1.5
  text "PI10" at 167.7,80.53 h1.5
  text "VREF+" at 40.18,80.42 h1 r90
  text "VREF+" at 123.4,80.42 h1 r90
  text "PI9" at 77.038,78.12 h1.5
  text "PI9" at 160.257,78.12 h1.5
  text "PH5" at 6.113,78.07 h1.5
  text "PH5" at 89.333,78.07 h1.5
  text "PA3" at 14.32,78.04 h1.5
  text "PA3" at 97.54,78.04 h1.5
  text "PI8" at 84.48,77.99 h1.5
  text "PI8" at 167.7,77.99 h1.5
  text "NC" at 6.068,75.65 h1.5
  text "NC" at 89.288,75.65 h1.5
  text "PA4" at 14.32,75.56 h1.5
  text "PA4" at 97.54,75.56 h1.5
  text "PC13" at 75.697,75.42 h1.5
  text "PC13" at 158.917,75.42 h1.5
  text "PI7" at 84.48,75.4 h1.5
  text "PI7" at 167.7,75.4 h1.5
  text "PA5" at 6.188,73 h1.5
  text "PI5" at 84.48,73.01 h1.5
  text "PA5" at 89.408,73 h1.5
  text "PI5" at 167.7,73.01 h1.5
  text "PI6" at 77.04,72.94 h1.5
  text "PI6" at 160.26,72.94 h1.5
  text "PA6" at 14.32,72.8 h1.5
  text "PA6" at 97.54,72.8 h1.5
  text "PA7" at 6.196,70.42 h1.5
  text "PA7" at 89.416,70.42 h1.5
  text "PC4" at 14.32,70.34 h1.5
  text "PI4" at 77.044,70.34 h1.5
  text "PC4" at 97.54,70.34 h1.5
  text "PI4" at 160.264,70.34 h1.5
  text "VDD" at 84.481,70.32 h1.5
  text "VDD" at 167.701,70.32 h1.5
  text "PC5" at 6.113,67.9 h1.5
  text "PC5" at 89.333,67.9 h1.5
  text "PB0" at 14.32,67.81 h1.5
  text "PB0" at 97.54,67.81 h1.5
  text "PE1" at 84.48,67.78 h1.5
  text "PE1" at 167.7,67.78 h1.5
  text "PDR_ON" at 69.35,67.56 h1.5
  text "PDR_ON" at 152.57,67.56 h1.5
  text "PB1" at 6.381,65.28 h1.5
  text "PB1" at 89.601,65.28 h1.5
  text "PE0" at 76.52,65.243 h1.5
  text "PE0" at 159.74,65.243 h1.5
  text "PB9" at 84.48,65.24 h1.5
  text "PB9" at 167.7,65.24 h1.5
  text "PB2" at 14.32,65.21 h1.5
  text "PB2" at 97.54,65.21 h1.5
  text "PF12" at 14.32,62.72 h1.5
  text "PB8" at 76.515,62.703 h1.5
  text "PF12" at 97.54,62.72 h1.5
  text "PB8" at 159.735,62.703 h1.5
  text "PF11" at 5.71,62.7 h1.5
  text "PB7" at 84.48,62.7 h1.5
  text "PF11" at 88.93,62.7 h1.5
  text "PB7" at 167.7,62.7 h1.5
  text "PF13" at 5.525,60.22 h1.5
  text "PF13" at 88.745,60.22 h1.5
  text "PF14" at 14.32,60.202 h1.5
  text "PF14" at 97.54,60.203 h1.5
  text "PB6" at 76.518,60.163 h1.5
  text "PB6" at 159.738,60.163 h1.5
  text "PB5" at 84.48,60.16 h1.5
  text "PB5" at 167.7,60.16 h1.5
  text "PG0" at 14.32,57.67 h1.5
  text "PG0" at 97.54,57.67 h1.5
  text "PF15" at 5.517,57.621 h1.5
  text "PB4" at 76.521,57.624 h1.5
  text "PF15" at 88.737,57.621 h1.5
  text "PB4" at 159.741,57.624 h1.5
  text "PB3" at 84.48,57.62 h1.5
  text "PB3" at 167.7,57.62 h1.5
  text "PG1" at 6.232,55.081 h1.5
  text "PE7" at 14.32,55.091 h1.5
  text "PG15" at 75.615,55.084 h1.5
  text "PG14" at 84.48,55.1 h1.5
  text "PG1" at 89.452,55.081 h1.5
  text "PE7" at 97.54,55.091 h1.5
  text "PG15" at 158.835,55.084 h1.5
  text "PG14" at 167.7,55.1 h1.5
  text "PE8" at 6.193,52.67 h1.5
  text "PE8" at 89.413,52.67 h1.5
  text "PE9" at 14.32,52.57 h1.5
  text "PG13" at 75.623,52.584 h1.5
  text "PE9" at 97.54,52.57 h1.5
  text "PG13" at 158.843,52.584 h1.5
  text "PG12" at 84.48,52.56 h1.5
  text "PG12" at 167.7,52.56 h1.5
  text "PE10" at 5.452,50.13 h1.5
  text "PE10" at 88.672,50.13 h1.5
  text "PE11" at 14.32,50.12 h1.5
  text "PE11" at 97.54,50.12 h1.5
  text "PG11" at 75.808,50.045 h1.5
  text "PG11" at 159.028,50.045 h1.5
  text "PG10" at 84.48,50.02 h1.5
  text "PG10" at 167.7,50.02 h1.5
  text "PE12" at 5.46,47.717 h1.5
  text "PE12" at 88.68,47.717 h1.5
  text "PE13" at 14.32,47.68 h1.5
  text "PE13" at 97.54,47.68 h1.5
  text "PG9" at 76.366,47.505 h1.5
  text "PG9" at 159.586,47.505 h1.5
  text "PD7" at 84.48,47.48 h1.5
  text "PD7" at 167.7,47.48 h1.5
  text "PE14" at 5.454,45.172 h1.5
  text "PE14" at 88.674,45.172 h1.5
  text "PE15" at 14.32,45.055 h1.5
  text "PE15" at 97.54,45.055 h1.5
  text "PD6" at 76.443,44.965 h1.5
  text "PD6" at 159.663,44.965 h1.5
  text "PD5" at 84.48,44.94 h1.5
  text "PD5" at 167.7,44.94 h1.5
  text "PB10" at 5.452,42.643 h1.5
  text "PB10" at 88.672,42.643 h1.5
  text "PB11" at 14.32,42.522 h1.5
  text "PB11" at 97.54,42.522 h1.5
  text "PD4" at 76.446,42.426 h1.5
  text "PD4" at 159.666,42.426 h1.5
  text "PD3" at 84.48,42.4 h1.5
  text "PD3" at 167.7,42.4 h1.5
  text "GND" at 5.726,40.114 h1.5
  text "GND" at 88.946,40.114 h1.5
  text "PD1" at 84.48,39.97 h1.5
  text "PD1" at 167.7,39.97 h1.5
  text "PH6" at 14.32,39.87 h1.5
  text "PD2" at 76.453,39.886 h1.5
  text "PH6" at 97.54,39.87 h1.5
  text "PD2" at 159.673,39.886 h1.5
  text "PH8" at 14.32,37.53 h1.5
  text "PH8" at 97.54,37.53 h1.5
  text "PC12" at 84.48,37.43 h1.5
  text "PC12" at 167.7,37.43 h1.5
  text "PD0" at 76.445,37.346 h1.5
  text "PD0" at 159.665,37.346 h1.5
  text "PH7" at 6.121,37.29 h1.5
  text "PH7" at 89.341,37.29 h1.5
  text "PC11" at 75.882,34.977 h1.5
  text "PC11" at 159.102,34.977 h1.5
  text "PC10" at 84.48,34.89 h1.5
  text "PC10" at 167.7,34.89 h1.5
  text "PH10" at 14.32,34.81 h1.5
  text "PH10" at 97.54,34.81 h1.5
  text "PH9" at 6.118,34.75 h1.5
  text "PH9" at 89.338,34.75 h1.5
  text "PA15" at 75.764,32.438 h1.5
  text "PA15" at 158.984,32.438 h1.5
  text "PH12" at 14.32,32.39 h1.5
  text "PH12" at 97.54,32.39 h1.5
  text "PA14" at 84.48,32.35 h1.5
  text "PA14" at 167.7,32.35 h1.5
  text "PH11" at 5.56,32.28 h1.5
  text "PH11" at 88.78,32.28 h1.5
  text "PB12" at 14.32,29.745 h1.5
  text "PA10" at 75.774,29.748 h1.5
  text "PA9" at 84.48,29.74 h1.5
  text "PB12" at 97.54,29.745 h1.5
  text "PA10" at 158.994,29.748 h1.5
  text "PA9" at 167.7,29.74 h1.5
  text "VDD" at 5.81,29.63 h1.5
  text "VDD" at 89.03,29.63 h1.5
  text "PB13" at 5.45,27.277 h1.5
  text "PB13" at 88.67,27.277 h1.5
  text "PB14" at 14.32,27.235 h1.5
  text "PB14" at 97.54,27.235 h1.5
  text "PA8" at 76.515,27.208 h1.5
  text "PC9" at 84.48,27.2 h1.5
  text "PA8" at 159.735,27.208 h1.5
  text "PC9" at 167.7,27.2 h1.5
  text "PB15" at 5.442,24.744 h1.5
  text "PB15" at 88.662,24.744 h1.5
  text "PD8" at 14.32,24.706 h1.5
  text "PD8" at 97.54,24.706 h1.5
  text "PC8" at 76.44,24.669 h1.5
  text "PC7" at 84.48,24.66 h1.5
  text "PC8" at 159.66,24.669 h1.5
  text "PC7" at 167.7,24.66 h1.5
  text "PD9" at 6.118,22.191 h1.5
  text "PD9" at 89.338,22.191 h1.5
  text "PD10" at 14.32,22.177 h1.5
  text "PD10" at 97.54,22.177 h1.5
  text "PC6" at 76.443,22.129 h1.5
  text "PG8" at 84.48,22.12 h1.5
  text "PC6" at 159.663,22.129 h1.5
  text "PG8" at 167.7,22.12 h1.5
  text "APM32F407IG" at 60.035,20.09 h2.5
  text "APM32F407IG" at 143.255,20.09 h2.5
  text "PD11" at 5.56,19.658 h1.5
  text "PD12" at 14.32,19.647 h1.5
  text "PI3" at 84.48,19.67 h1.5
  text "PD11" at 88.78,19.658 h1.5
  text "PD12" at 97.54,19.647 h1.5
  text "PI3" at 167.7,19.67 h1.5
  text "PG7" at 76.369,19.529 h1.5
  text "PG7" at 159.589,19.53 h1.5
  text "MINIBOARD V1.0" at 64.11,18.46 h1.5
  text "MINIBOARD V1.0" at 147.33,18.46 h1.5
  text "PD13" at 5.375,17.125 h1.5
  text "PD14" at 14.32,17.118 h1.5
  text "PD13" at 88.595,17.125 h1.5
  text "PD14" at 97.54,17.118 h1.5
  text "PI2" at 77.05,16.97 h1.5
  text "PI1" at 84.48,16.97 h1.5
  text "PI2" at 160.27,16.97 h1.5
  text "PI1" at 167.7,16.97 h1.5
  text "PD15" at 5.367,14.592 h1.5
  text "PG2" at 14.32,14.589 h1.5
  text "PD15" at 88.587,14.592 h1.5
  text "PG2" at 97.54,14.589 h1.5
  text "PH15" at 84.48,14.51 h1.5
  text "PH15" at 167.7,14.51 h1.5
  text "PI0" at 77.043,14.37 h1.5
  text "PI0" at 160.262,14.37 h1.5
  text "PH13" at 84.48,12.12 h1.5
  text "PH13" at 167.7,12.12 h1.5
  text "PG3" at 6.047,12.059 h1.5
  text "PG4" at 14.32,12.059 h1.5
  text "PG3" at 89.267,12.059 h1.5
  text "PG4" at 97.54,12.059 h1.5
  text "PH14" at 75.7,12.05 h1.5
  text "PH14" at 158.92,12.05 h1.5
  text "PG6" at 14.32,9.54 h1.5
  text "PG6" at 97.54,9.54 h1.5
  text "PA13" at 75.772,9.43 h1.5
  text "PA13" at 158.992,9.43 h1.5
  text "+5.0V" at 84.48,9.41 h1.5
  text "+5.0V" at 167.7,9.41 h1.5
  text "PG5" at 6.04,9.24 h1.5
  text "PG5" at 89.26,9.24 h1.5
  text "RESET" at 68.66,0.94 h1.5
  text "RESET" at 151.88,0.94 h1.5
  text "KEY1" at 20.06,0.45 h1.5
  text "KEY1" at 103.28,0.45 h1.5
  text "KEY2" at 31.25,0.42 h1.5
  text "KEY2" at 114.47,0.42 h1.5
